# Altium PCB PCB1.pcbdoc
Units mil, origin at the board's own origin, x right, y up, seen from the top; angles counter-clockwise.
Board outline 2911 x 3003 mil, 2 copper layers (Top Layer, Bottom Layer); 29 components, 22 nets, 104 pads, 74 vias.
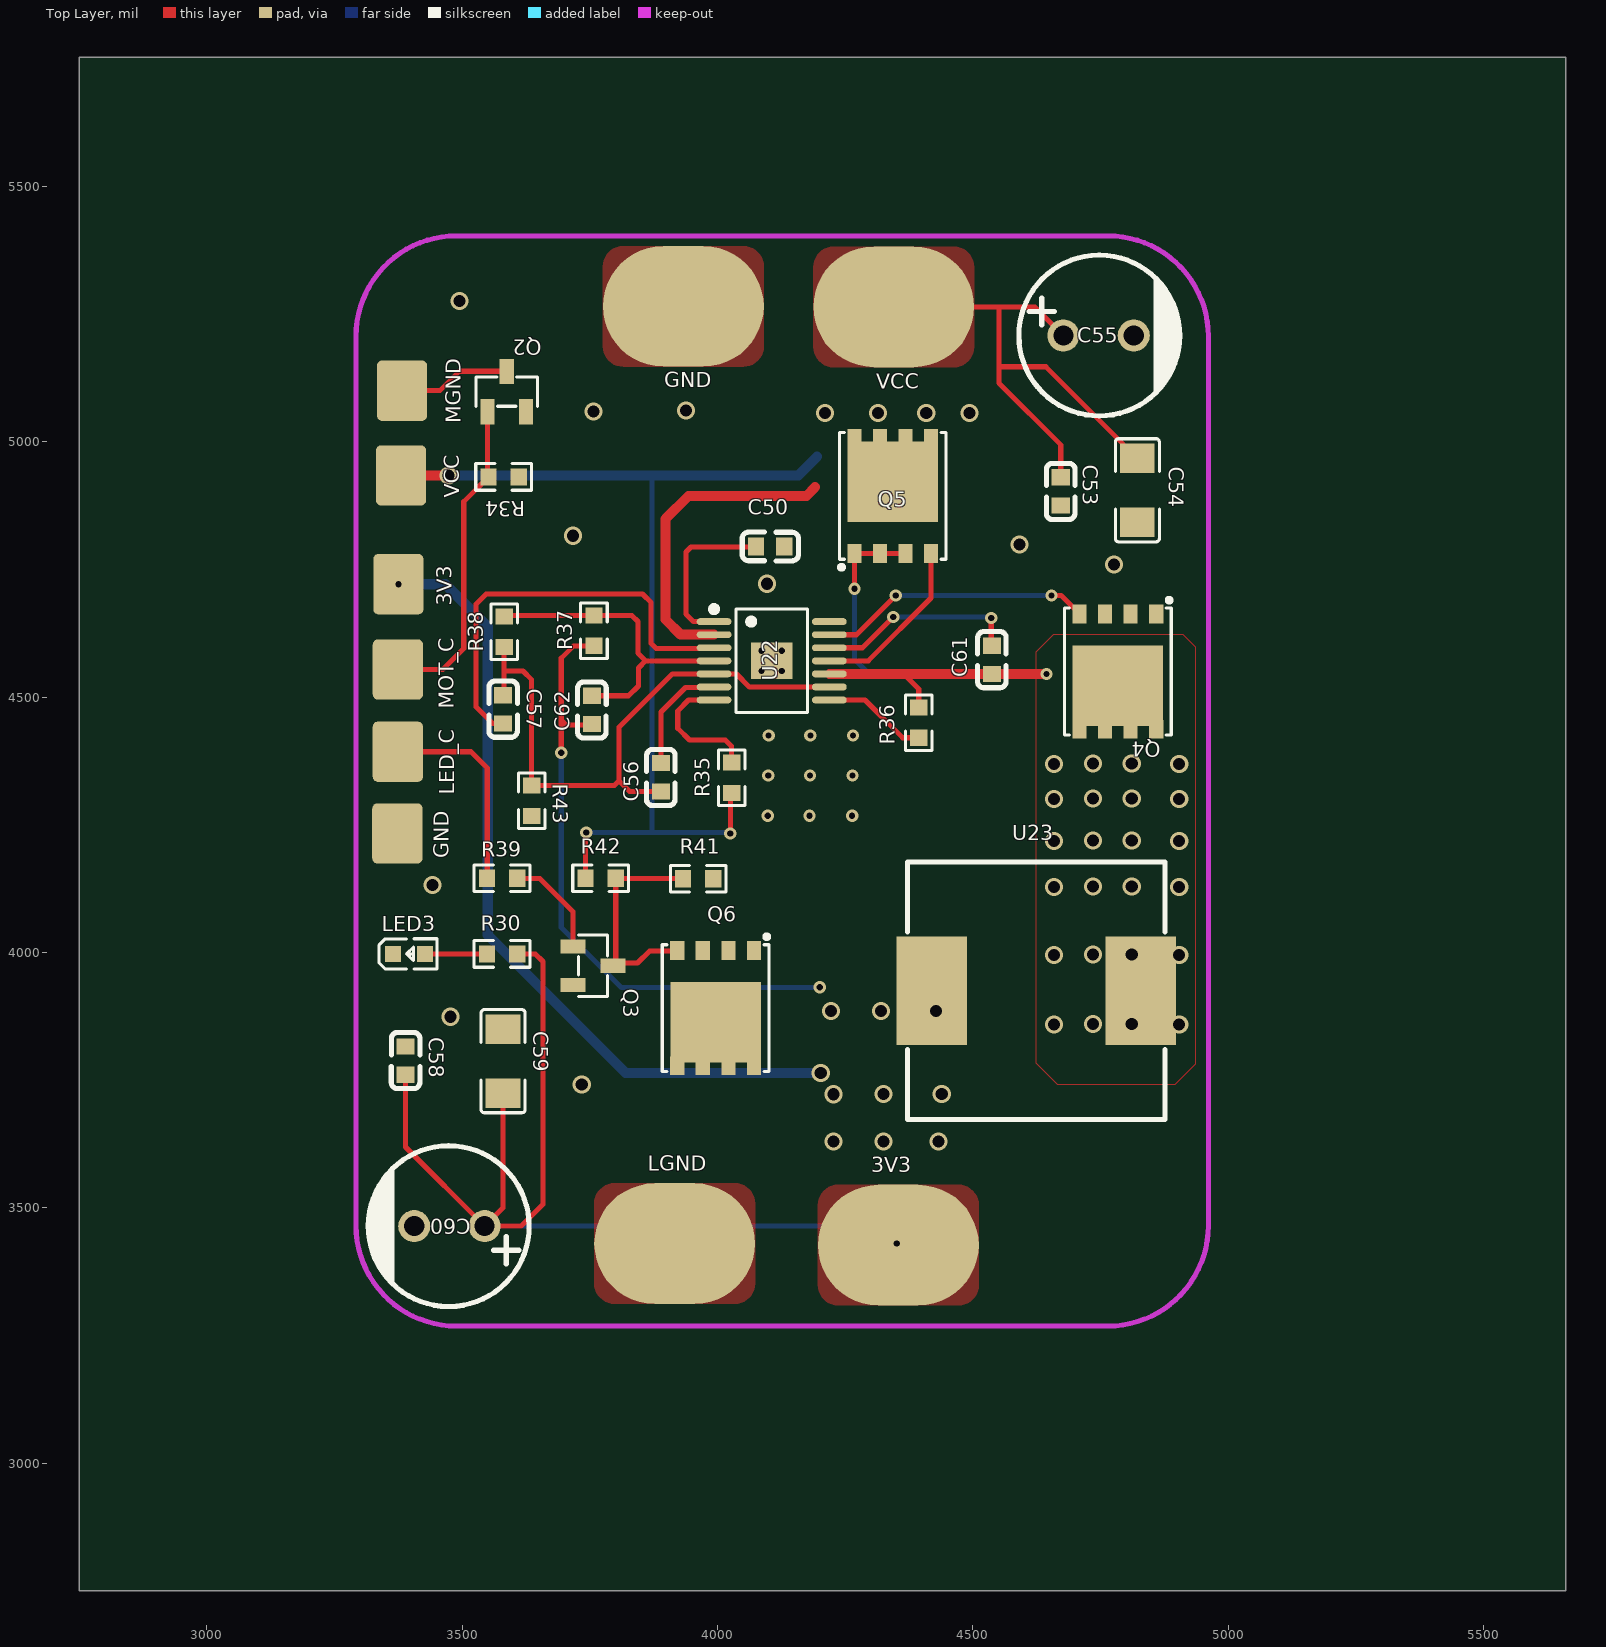
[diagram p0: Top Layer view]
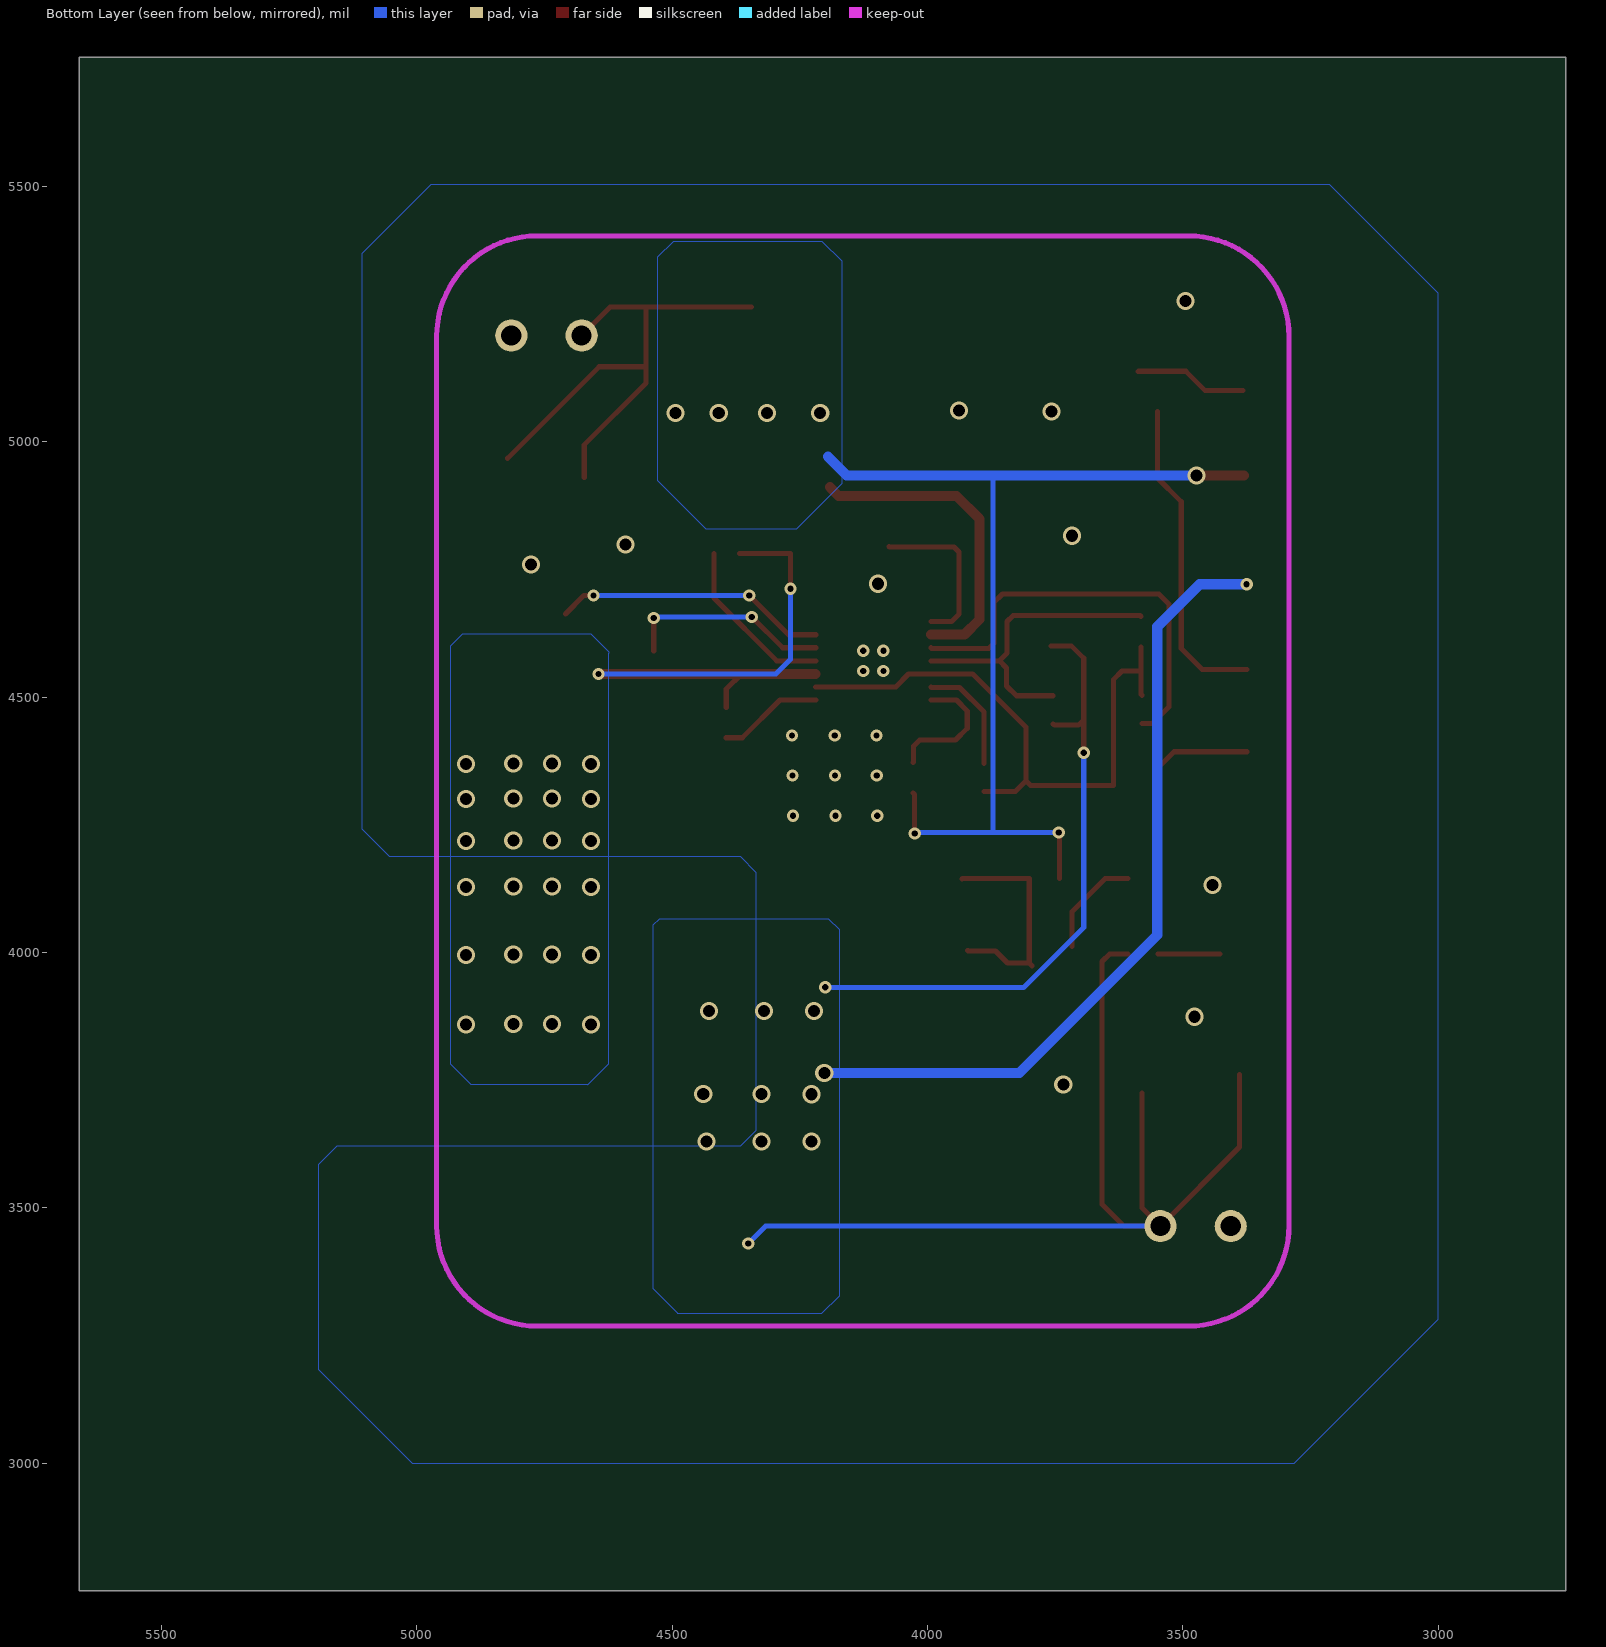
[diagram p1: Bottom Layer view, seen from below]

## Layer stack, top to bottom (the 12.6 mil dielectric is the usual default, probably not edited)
Top Layer: signal copper (thickness not stored)
Dielectric: dielectric 12.6, FR-4, Dk 4.8
Bottom Layer: signal copper (thickness not stored)

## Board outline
5661,2750 2750,2750 2750,5753 5661,5753

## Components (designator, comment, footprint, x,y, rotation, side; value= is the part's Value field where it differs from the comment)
C50 "CAP_0603" C0603 4103,4795 r180 top
C53 "CAP_0603" C0603 4672,4903 r90 top
C54 "CL31A106KBHNNNE" C1206 4822,4905 r90 top
C55 "KM227M035F12RR0VH2FP0" CAP-TH_BD8.0-P3.50-D0.6-FD 4746,5208 r0 top
C56 "CAP_0603" C0603 3889,4343 r90 top
C57 "CAP_0603" C0603 3580,4476 r270 top
C58 "CAP_0603" C0603 3389,3788 r270 top
C59 "CL31A106KBHNNNE" C1206 3580,3787 r270 top
C60 "KM227M035F12RR0VH2FP0" CAP-TH_BD8.0-P3.50-D0.6-FD 3475,3464 r180 top
C61 "CAP_0603" C0603 4537,4573 r270 top
C62 "CAP_0603" C0603 3754,4475 r90 top
LED3 "NCD0603R1_C84263" LED0603-RD_RED 3396,3997 r0 top
Q2 "AO3400A_C347475" SOT-23-3_L2.9-W1.3-P1.90-LS2.4-BR 3587.13,5098.08 r270 top
Q3 "SS8050_C2150" SOT-23-3_L2.9-W1.3-P1.90-LS2.4-BR 3756,3974 r180 top
Q4 "BSC027N04LSG" PG-TDSON-8_L5.0-W6.0-P1.27-LS6.2-BL-EP 4784,4550 r180 top
Q5 "BSC027N04LSG" PG-TDSON-8_L5.0-W6.0-P1.27-LS6.2-BL-EP 4343,4894 r0 top
Q6 "BSC027N04LSG" PG-TDSON-8_L5.0-W6.0-P1.27-LS6.2-BL-EP 3996,3891 r180 top
R30 "0603WAF1001T5E" R0603 3578,3997 r0 top
R34 "Res_0603" R0603 3581,4931 r0 top
R35 "Res_0603" R0603 4028,4342 r270 top
R36 "Res_0603" R0603 4394,4450 r90 top
R37 "Res_0603" R0603 3758,4630 r270 top
R38 "Res_0603" R0603 3582,4628 r90 top
R39 "Res_0603" R0603 3578,4145 r0 top
R41 "Res_0603" R0603 3962,4144 r0 top
R42 "Res_0603" R0603 3771,4145 r180 top
R43 "Res_0603" R0603 3636,4297 r270 top
U22 "LM3150MHX/NOPB" HTSSOP-14_L5.0-W4.4-P0.65-LS6.4-BL-EP 4106,4571 r270 top
U23 "B82477G4102M000" IND-SMD_L12.8-W12.8_B953AS 4624,3925 r180 top

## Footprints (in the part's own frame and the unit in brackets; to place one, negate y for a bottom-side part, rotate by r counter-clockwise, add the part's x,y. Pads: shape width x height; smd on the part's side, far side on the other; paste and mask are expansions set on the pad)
C0603 [mm]
  rect 0.8x0.9 smd: 1(-0.7,0) 2(0.7,0)
  silkscreen extent -1.41,-0.71 1.39,0.72
C1206 [mm]
  rect 1.485x1.728 smd: 1(-1.593,0) 2(1.593,0)
  silkscreen extent -2.56,-1.09 2.56,1.09
CAP-TH_BD8.0-P3.50-D0.6-FD [mm]
  round 1.6 hole 1: 1(-1.75,0) 2(1.75,0)
  silkscreen extent -3.96,-4 4.04,4
HTSSOP-14_L5.0-W4.4-P0.65-LS6.4-BL-EP [mm]
  oval 0.343x1.731 smd: 1(-1.95,-2.866) 2(-1.3,-2.866) 3(-0.65,-2.866) 4(0,-2.866) 5(0.65,-2.866) 6(1.3,-2.866) 7(1.95,-2.866) 8(1.95,2.866) 9(1.3,2.866) 10(0.65,2.866) 11(0,2.866) 12(-0.65,2.866) 13(-1.3,2.866) 14(-1.95,2.866)
  rect 1.83x2.055 smd: 15(0,0)
  silkscreen extent -2.72,-3.02 2.58,1.77
IND-SMD_L12.8-W12.8_B953AS [mm]
  rect 3.5x5.4 smd: 1(-5.2,0) 2(5.2,0)
  silkscreen extent -6.4,-6.4 6.4,6.4
LED0603-RD_RED [mm]
  rect 0.8x0.8 smd: 1(-0.8,-0.003) 2(0.8,0.003)
  silkscreen extent -1.49,-0.75 1.39,0.76
PG-TDSON-8_L5.0-W6.0-P1.27-LS6.2-BL-EP [mm]
  rect 0.7x0.925 smd: 1(-1.905,-2.865) 2(-0.635,-2.865) 3(0.635,-2.865) 4(1.905,-2.865) 5(1.905,2.865) 6(0.635,2.865) 7(-0.635,2.865) 8(-1.905,2.865)
  rect 4.5x4 smd: 9(0,0.705)
  silkscreen extent -2.66,-3.66 2.65,3.15
R0603 [mil]
  rect 31.75x34.02 smd: 1(-29.66,0) 2(29.66,0)
  silkscreen extent -55,-26 55,26
SOT-23-3_L2.9-W1.3-P1.90-LS2.4-BR [mm]
  rect 1.25x0.7 smd: 1(1,-0.95) 2(1,0.95) 3(-1,0)
  silkscreen extent -0.73,-1.53 0.73,1.53

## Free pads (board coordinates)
  rrect20% 98.43x118.11 smd: 21(3373,4233) 21(3374,4393) 21(3374,4554) 21(3375,4721) 21(3380.13,4934.08) 21(3382.13,5100.08)
  oval 314.96x236.22 smd: 23(3916,3430) 23(3933,5265) 23(4345,5264) 23(4354,3427)

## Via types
v1: diameter 35.43, hole 23.62, Top Layer to Bottom Layer, 49 vias
v2: diameter 24.02, hole 12.2, Top Layer to Bottom Layer, 21 vias
v3: diameter 24, hole 12, Top Layer to Bottom Layer, 4 vias

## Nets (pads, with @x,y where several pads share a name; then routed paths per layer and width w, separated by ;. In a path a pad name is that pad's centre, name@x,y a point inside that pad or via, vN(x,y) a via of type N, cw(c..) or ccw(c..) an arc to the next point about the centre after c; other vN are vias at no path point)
3V3: C58.2 C59.2 C60.1 C62.1 pad.21@3375,4721 pad.23@4354,3427 R30.2 R37.2 U23.2 | length 4919.2
  Top Layer w10: C58.2 3389,3618.9 C60.1 ; C59.2 3580,3500.1 C60.1 ; R30.2 3643,3997 3658,3982 3658,3507 3615,3464 C60.1 ; v2(3694,4391) 3694,4455 ; C62.1 3751.56,4445 3704,4445 3694,4455 ; R37.2 3718.34,4600.34 3694,4576 3694,4455
  Bottom Layer w10: C60.1 4317,3464 v2(4351,3430) ; v2(3694,4391) 3694,4049 3812,3931 4199,3931 v2(4200,3932)
  Bottom Layer w19.68: v2(3375,4721) 3467,4721 3550,4638 3550,4034 3820,3764 v1(4202,3764)
  other v1: 4227,3630 4324.61,3630 4432.47,3630 4227,3722.3 4325,3723 4439,3723 4222.27,3885.19 4319.87,3885.19 4427.73,3885.19
$1N3958: LED3.2 R30.1 | length 120.9
  Top Layer w10: LED3.2 3548.2,3997.14 R30.1
$1N4069: C50.2 U22.1 | length 324.8
  Top Layer w10: U22.1 3952.67,4647.77 3938,4662.44 3938,4784 3948,4794 4074.44,4794 C50.2
$1N4674: R35.1 U22.7 | length 266.2
  Top Layer w10: U22.7 3943.23,4494.23 3922,4473 3922,4439 3945,4416 4015,4416 4027,4404 4027,4372.66 R35.1
$1N4765: C56.2 U22.6 | length 224.8
  Top Layer w10: C56.2 3889,4471 3937,4519 3992.36,4519 U22.6
$1N4847: C57.2 U22.3 | length 833.8
  Top Layer w10: C57.2 3559.56,4448.44 3527,4481 3527,4682 3547,4702 3853,4702 3870,4685 3870,4605 3880,4595 3991.59,4595 U22.3
$1N5111: R36.1 U22.8 | length 205.8
  Top Layer w10: U22.8 4288.77,4494.23 4362.66,4420.34 R36.1
$1N5322: Q5.4 U22.11 | length 337.3
  Top Layer w10: U22.11 4295,4571 4418,4694 Q5.4
$1N5328: Q4.4 U22.13 | length 537
  Top Layer w10: U22.13 4272.18,4622.18 v2(4349,4699) ; v2(4654,4699) 4672.81,4699 Q4.4
  Bottom Layer w10: v2(4349,4699) v2(4654,4699)
$1N5815: C61.1 U22.12 | length 407.5
  Top Layer w10: U22.12 4283.59,4596.59 v2(4344,4657) ; C61.1@4536,4590.56 v2(4536,4655)
  Bottom Layer w10: v2(4344,4657) 4534,4657 v2(4536,4655)
$1N6183: C62.2 R37.1 R38.2 U22.4 | length 639.2
  Top Layer w10: R38.2 3584,4659.66 R37.1 3758.34,4660 3832,4660 3844,4648 3844,4586 3859,4571 ; C62.2 3825.56,4502.56 3844.98,4521.98 3844.98,4556.98 3859,4571 ; U22.4 3859,4571
$1N15337: C61.2 Q4.5 Q4.6 Q4.7 Q4.8 Q4.9 Q5.1 Q5.2 Q5.3 R36.2 U22.10 U23.1 | length 1195.4
  Top Layer w10: v2(4268,4712) Q5.1 Q5.2 Q5.3 ; 4364.38,4545.41 4394,4515.79 R36.2
  Top Layer w19.68: U22.10 4364.38,4545.41 C61.2 ; C61.2 v2@4641,4545.44
  Bottom Layer w10: v2(4268,4712) 4268,4574 4297,4545 v2(4644,4545)
  other v1: 4659,3858.96 4904,3858.96 4735,3859.96 4811,3859.96 4659,3994.89 4904,3994.89 4735,3995.89 4811,3995.89 4659,4128.17 4904,4128.17 4735,4129.17 4811,4129.17 4659,4218.35 4904,4218.35 4735,4219.35 4811,4219.35 4659,4300.79 4904,4300.79 4735,4301.79 4811,4301.79 4659,4369 4904,4369 4735,4370 4811,4370
$1N15416: Q3.1 R39.2 | length 204.7
  Top Layer w10: R39.2 3652,4145 3716.63,4080.37 Q3.1
$1N18673: Q3.3 Q6.4 R41.1 R42.1 | length 435.8
  Top Layer w10: Q3.3 Q3.3@3800.66,3979.29 ; Q6.4 3920.2,4003 3867,4003 3843.29,3979.29 Q3.3@3800.66,3979.29 ; R41.1 3931.34,4145 R42.1 Q3.3@3800.66,3979.29
AGND: C56.1 C57.1 R38.1 R43.1 U22.5 U22.9 | length 1200.1
  Top Layer w10: C57.1 3582,4505.56 3582,4551.12 ; R38.1 3582,4551.12 ; C56.1 3827.56,4315.44 3807,4336 ; U22.9 4062.18,4519.82 4037,4545 3993.59,4545 U22.5 3911.41,4545.41 3807,4441 3807,4336 ; 3582,4551.12 3618.88,4551.12 3636,4534 R43.1 3797.66,4326.66 3807,4336
GND: C50.1 C53.1 C54.1 C55.2 C58.1 C59.1 C60.2 LED3.1 pad.21@3373,4233 pad.23@3933,5265 Q2.2 Q3.2 Q4.1 Q4.2 Q4.3 Q6.1 Q6.2 Q6.3 R34.2 R41.2 R43.2 U22.14
  other v1: 3734,3741 3477,3874 3442,4132 4097,4722 4776,4760 4591,4799 3717,4816 3757,5059 3938,5061 3495,5276
  other v2: 4098.2,4267.52 4179.95,4267.52 4263.5,4267.52 4099.1,4346.26 4180.85,4346.26 4264.4,4346.26 4100,4425 4181.75,4425 4265.3,4425
LED_CONTROL: pad.21@3374,4393 R39.1 | length 404.5
  Top Layer w10: pad.21@3374,4393 3517,4393 3549,4361 3549,4145.66 R39.1
LED_GND: pad.23@3916,3430 Q6.5 Q6.6 Q6.7 Q6.8 Q6.9
MOTOR_CONTROL: pad.21@3374,4554 Q2.1 R34.1 | length 630.4
  Top Layer w10: pad.21@3374,4554 3462,4554 3503,4595 3503,4882.66 R34.1 3549.73,4932.61 Q2.1
MOTOR_GND: pad.21@3382.13,5100.08 Q2.3 | length 220.9
  Top Layer w10: pad.21@3382.13,5100.08 3456.08,5100.08 3494,5138 3586.57,5138 Q2.3
VCC: C53.2 C54.2 C55.1 pad.21@3380.13,4934.08 pad.23@4345,5264 Q5.5 Q5.6 Q5.7 Q5.8 Q5.9 R35.2 R42.2 U22.2 | length 3690.3
  Top Layer w10: R42.2 3741.34,4233.34 v2(3743,4235) ; v2(4025,4233) 4025,4309.34 R35.2 ; pad.23@4345,5264 4551.22,5264 ; C53.2 4672,4994 4551.22,5114.78 4551.22,5146.91 ; C55.1 4621.1,5264 4551.22,5264 ; C54.2 4642.79,5146.91 4551.22,5146.91 ; 4551.22,5146.91 4551.22,5264
  Top Layer w19.68: pad.21@3380.13,4934.08 v1(3473,4934.08) ; U22.2 3927.82,4622.18 3898.06,4651.94 3898.06,4849.06 3943,4894 4174,4894 4191,4911
  Bottom Layer w10: v2(3743,4235) 3871.49,4235 ; 3871.49,4933.49 3871.49,4235 ; v2(4025,4233) 4023,4235 3871.49,4235
  Bottom Layer w19.68: v1(3473,4934.08) 3871.49,4934.08 ; 3871.49,4933.49 3871.49,4934.08 ; 4195,4971 4158.08,4934.08 3871.49,4934.08
  other v1: 4210,5056 4313.86,5056 4408.68,5056 4493.56,5056
"": U22.15
  other v3: 4086.32,4551.31 4125.69,4551.31 4086.32,4590.68 4125.69,4590.68

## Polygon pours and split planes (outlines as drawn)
3V3 on Top Layer (solid, remove dead copper, pour order 0): 4188,4066 4525,4066 4538,4053 4538,3339 4490,3291 4206,3291 4169,3328 4169,4047
$1N15337 on Top Layer (solid, remove dead copper, pour order 1): 4911,4623 4935,4599 4935,3781 4895,3741 4665.94,3741 4624,3782.94 4624,4589 4658,4623
VCC on Top Layer (solid, remove dead copper, pour order 2): 4206,5392 4497,5392 4529,5360 4529,4925 4432,4828 4258,4828 4168,4918 4168,5354
LED_GND on Top Layer (solid, remove dead copper, pour order 3): 3722,3613 3787,3678 3826.82,3678 3861,3715.48 3861,3931 3884,3954 4116,3954 4118,3952 4118,3337 4074,3293 3750,3293 3722,3321
GND on Top Layer (solid, remove dead copper, pour order 4): 4875,5501 5411,4965 5411,4580 5015,4184 4366,4184 4349,4167 4349,3664 4363,3650 4984,3650 5023,3611 5023,3287 4846,3110 3224,3110 3033,3301 3033,5391 3018,5406 3113,5501
VCC on Bottom Layer (solid, remove dead copper, pour order 5): 4168,5354 4168,4918 4257,4829 4433,4829 4528,4924 4528,5362 4497,5393 4207,5393
3V3 on Bottom Layer (solid, remove dead copper, pour order 6): 4193.34,4065.34 4525.66,4065.34 4538,4053 4538,3342 4490,3294 4490,3293 4207,3293 4172,3328 4172,4044
$1N15337 on Bottom Layer (solid, remove dead copper, pour order 7): 4658,4623 4911,4623 4934.49,4599.51 4934.49,3782.49 4894.1,3742.1 4666.1,3742.1 4665,3741 4624,3782 4624,4586 4623,4587 4623,4588
GND on Bottom Layer (solid, remove dead copper, pour order 8): 4973,5503 5108,5368 5108,4242 5054,4188 4367,4188 4336,4157 4336,3651 4367,3620 5157,3620 5193,3584 5193,3184 5009,3000 3282,3000 3000,3282 3000,5291 3212,5503

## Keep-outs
Board Outline Layer:
  lines w10 net "": 3292,3465.1 ccw(c3488.85,3465.1) 3488.85,3268.25 4764.17,3268.25 ccw(c4764.17,3465.1) 4961.02,3465.1 4961.02,5206.4 ccw(c4764.17,5206.4) 4764.17,5403.25 3488.85,5403.25 ccw(c3488.85,5206.4) 3292,5206.4 3292,3465.1

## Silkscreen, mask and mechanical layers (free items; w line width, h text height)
Top Silkscreen Layer:
  text "GND" at 3895.51,5106.99 h29.2
  text "VCC" at 4310.51,5103.99 h29.2
  text "MGND" at 3497.01,5036.22 h29.2 r90
  text "VCC" at 3494.38,4889.88 h29.2 r90
  text "3V3" at 3479.01,4678.51 h29.2 r90
  text "MOT_C" at 3483.01,4476.94 h29.2 r90
  text "LED_C" at 3484.01,4308.94 h29.2 r90
  text "GND" at 3474.01,4184.51 h29.2 r90
  text "LGND" at 3863.22,3572.99 h29.2
  text "3V3" at 4300.51,3569.99 h29.2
